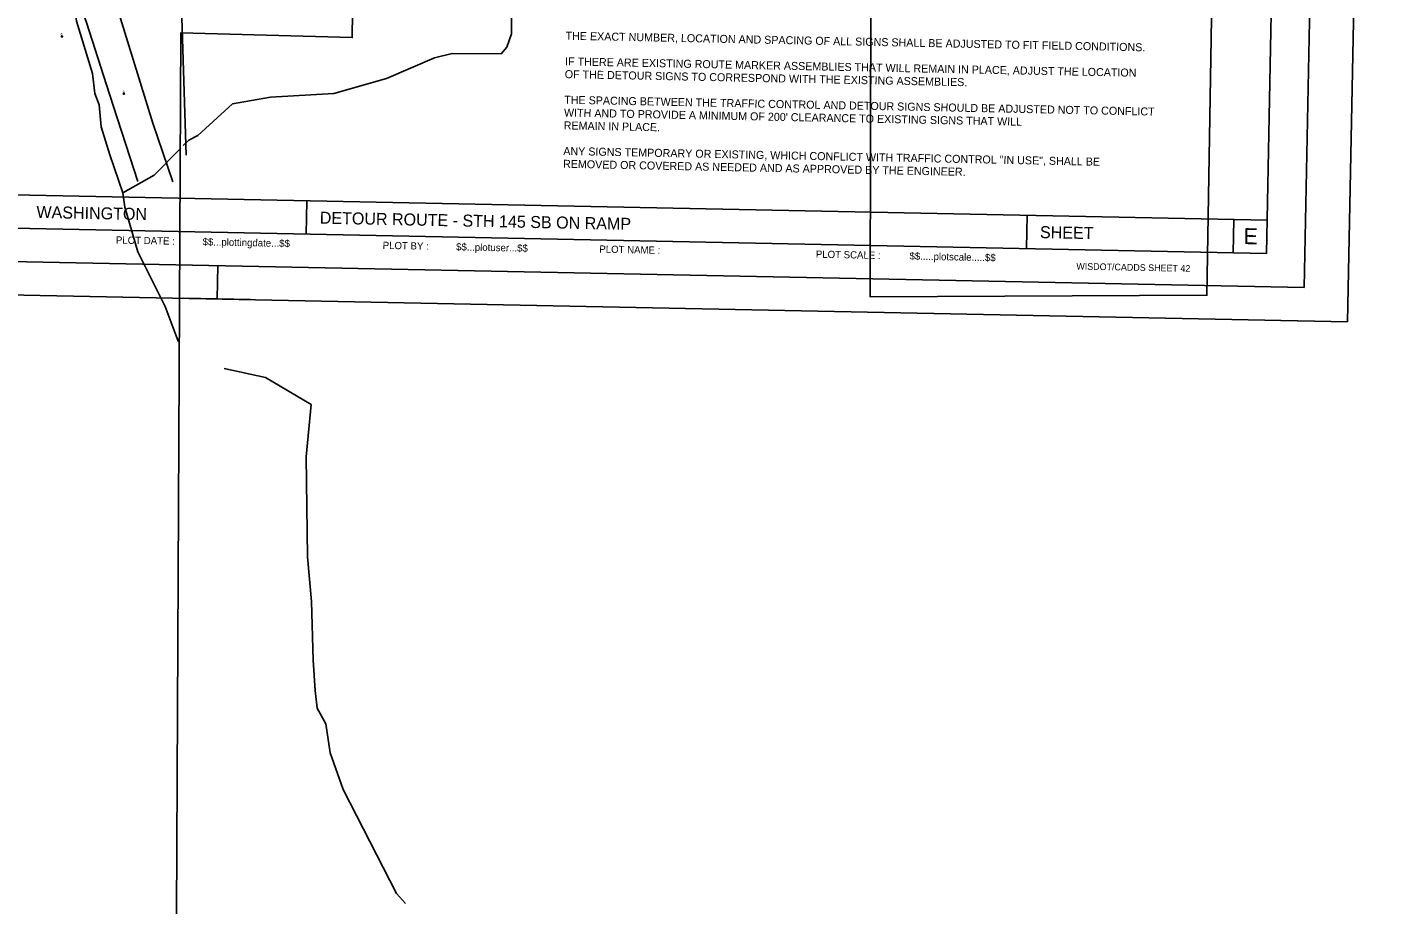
# Model space of a CAD drawing. Extents: x 331323 to 388339, y 121519 to 205315.
# Drawn here: x 361475 to 371668, y 121807 to 128453 of the extents above; entities that cross this region are included whole.
import ezdxf

# ---------------------------------------------------------------- set-up
doc = ezdxf.new("R2010")
doc.units = 0
for name, color, linetype in [('CA-TEXT', 7, 'Continuous'), ('E_SOIL_BORE1 [KAPUR_CADDS_LEVELS]', 7, 'Continuous'), ('E_SOIL_BORE2 [KAPUR_CADDS_LEVELS]', 7, 'Continuous'), ('Level 2', 7, 'Continuous'), ('Level 21', 7, 'Continuous'), ('Level 4', 7, 'Continuous'), ('Level 57', 7, 'Continuous'), ('P_MARK', 7, 'Continuous'), ('P_RDWY_Text', 7, 'Continuous'), ('PLT_Sheet_Border', 7, 'Continuous'), ('PLT_Sheet_Info', 7, 'Continuous')]:
    doc.layers.add(name, color=color, linetype=linetype)

msp = doc.modelspace()

# ---------------------------------------------------------------- linework, layer by layer
at = {"layer": 'Level 2'}
for points in [[(361798, 130230), (361948, 129376), (362176, 128518), (362416, 127734), (362567, 127294)], [(361525, 129517), (361674, 129157), (361920, 128489), (362093, 127950), (362304, 127295)]]:
    msp.add_lwpolyline(points, dxfattribs=at)
at = {"layer": 'Level 21'}
msp.add_lwpolyline([(375076, 132102), (370943, 132185), (370895, 130740), (370392, 130742), (370319, 126443), (367795, 126431), (367808, 132231), (366120, 132233), (366136, 131513), (366392, 131512), (366390, 130783), (366031, 131091), (365085, 131112), (365090, 131495), (364323, 131507), (364297, 130440), (364589, 130440), (364573, 129673), (363929, 129678), (363912, 128375), (362626, 128410), (362594, 121807)], dxfattribs=at)
at = {"layer": 'Level 4'}
msp.add_lwpolyline([(362628, 130213), (362617, 129083), (362666, 127494)], dxfattribs=at)
at = {"layer": 'Level 57'}
for points in [[(361568, 129209), (361699, 129008), (361748, 128907), (361764, 128807), (361813, 128698), (361845, 128498), (361966, 128105), (361982, 127955), (362014, 127871), (362029, 127705), (362094, 127496), (362192, 127212)], [(362645, 127565), (362687, 127607), (362754, 127640), (363015, 127879), (363299, 127927), (363775, 127956), (364168, 128069), (364528, 128224), (364661, 128256), (365028, 128253), (365071, 128302), (365105, 128402), (365108, 128727)], [(362192, 127212), (362426, 127343), (362627, 127546)], [(362192, 127212), (362207, 127103), (362304, 126769), (362509, 126359), (362607, 126099), (362619, 126087)], [(362951, 125895), (363263, 125827), (363603, 125624), (363566, 125232), (363576, 124482), (363606, 124149), (363619, 123707), (363633, 123482), (363649, 123348), (363714, 123231), (363746, 123014), (363843, 122738), (364245, 121959), (364311, 121884)]]:
    msp.add_lwpolyline(points, dxfattribs=at)
at = {"layer": 'P_MARK'}
for p, q in [((361731, 128383), (361741, 128383)), ((361736, 128388), (361736, 128378)), ((362195, 127954), (362205, 127954)), ((362200, 127959), (362200, 127949))]:
    msp.add_line(p, q, dxfattribs=at)
for centre in [(361736, 128383), (362200, 127954)]:
    msp.add_circle(centre, 5, dxfattribs=at)
for centre, radius, start, end in [((361736, 128383), 4.5, 89.9869, 179.9869), ((361736, 128383), 4, 89.9869, 179.9869), ((361736, 128383), 3.5, 89.9869, 179.9869), ((361736, 128383), 3, 89.9869, 179.9869), ((361736, 128383), 2.5, 89.9869, 179.9869), ((361736, 128383), 2, 89.9869, 179.9869), ((361736, 128383), 1.5, 89.9869, 179.9869), ((361736, 128383), 1, 89.9869, 179.9869), ((361736, 128383), 4.5, 269.9869, 359.9869), ((361736, 128383), 4, 269.9869, 359.9869), ((361736, 128383), 3.5, 269.9869, 359.9869), ((361736, 128383), 3, 269.9869, 359.9869), ((361736, 128383), 2.5, 269.9869, 359.9869), ((361736, 128383), 2, 269.9869, 359.9869), ((361736, 128383), 1.5, 269.9869, 359.9869), ((361736, 128383), 1, 269.9869, 359.9869), ((361736, 128383), 0.5, 269.9869, 359.9869), ((361736, 128383), 0.5, 89.9869, 179.9869), ((362200, 127954), 4.5, 89.9869, 179.9869), ((362200, 127954), 4, 89.9869, 179.9869), ((362200, 127954), 3.5, 89.9869, 179.9869), ((362200, 127954), 3, 89.9869, 179.9869), ((362200, 127954), 2.5, 89.9869, 179.9869), ((362200, 127954), 2, 89.9869, 179.9869), ((362200, 127954), 1.5, 89.9869, 179.9869), ((362200, 127954), 1, 89.9869, 179.9869), ((362200, 127954), 0.5, 89.9869, 179.9869), ((362200, 127954), 4.5, 269.9869, 359.9869), ((362200, 127954), 4, 269.9869, 359.9869), ((362200, 127954), 3.5, 269.9869, 359.9869), ((362200, 127954), 3, 269.9869, 359.9869), ((362200, 127954), 2.5, 269.9869, 359.9869), ((362200, 127954), 2, 269.9869, 359.9869), ((362200, 127954), 1.5, 269.9869, 359.9869), ((362200, 127954), 1, 269.9869, 359.9869), ((362200, 127954), 0.5, 269.9869, 359.9869)]:
    msp.add_arc(centre, radius, start, end, dxfattribs=at)
at = {"layer": 'P_RDWY_Text'}
msp.add_lwpolyline([(354598, 137585), (371594, 137243), (371373, 126245), (354376, 126587)], close=True, dxfattribs=at)
at = {"layer": 'PLT_Sheet_Border'}
for points in [[(354376, 126587), (371373, 126245), (371594, 137243), (354598, 137585)], [(354501, 126835), (371048, 126502), (371259, 136999), (354713, 137333)]]:
    msp.add_lwpolyline(points, close=True, dxfattribs=at)
at = {"layer": 'PLT_Sheet_Info'}
for p, q in [((370765, 126757), (370967, 136755)), ((355024, 127324), (370770, 127007)), ((363567, 126902), (363572, 127152)), ((355019, 127074), (370765, 126757)), ((368966, 126794), (368971, 127044)), ((370515, 126762), (370520, 127012)), ((371373, 126245), (371383, 126745)), ((362899, 126416), (362904, 126666)), ((362649, 126421), (363149, 126411)), ((370873, 126255), (371373, 126245))]:
    msp.add_line(p, q, dxfattribs=at)

# ---------------------------------------------------------------- texts
at = {"layer": 'CA-TEXT'}
for s, p in [('THE EXACT NUMBER, LOCATION AND SPACING OF ALL SIGNS SHALL BE ADJUSTED TO FIT FIELD CONDITIONS.', (365511, 128359)), ('IF THERE ARE EXISTING ROUTE MARKER ASSEMBLIES THAT WILL REMAIN IN PLACE, ADJUST THE LOCATION ', (365507, 128167)), ('OF THE DETOUR SIGNS TO CORRESPOND WITH THE EXISTING ASSEMBLIES. ', (365505, 128071)), ('THE SPACING BETWEEN THE TRAFFIC CONTROL AND DETOUR SIGNS SHOULD BE ADJUSTED NOT TO CONFLICT', (365501, 127879)), ("WITH AND TO PROVIDE A MINIMUM OF 200' CLEARANCE TO EXISTING SIGNS THAT WILL", (365499, 127783)), ('REMAIN IN PLACE.', (365497, 127687)), ('ANY SIGNS TEMPORARY OR EXISTING, WHICH CONFLICT WITH TRAFFIC CONTROL "IN USE", SHALL BE', (365494, 127495)), ('REMOVED OR COVERED AS NEEDED AND AS APPROVED BY THE ENGINEER.', (365492, 127399))]:
    msp.add_text(s, height=60, rotation=358.8462, dxfattribs=at).set_placement(p)
at = {"layer": 'E_SOIL_BORE1 [KAPUR_CADDS_LEVELS]'}
msp.add_text('B1', height=10, rotation=89.9869, dxfattribs=at).set_placement((361737, 128392))
at = {"layer": 'E_SOIL_BORE2 [KAPUR_CADDS_LEVELS]'}
for s, p in [('B1', (361740, 128390)), ('B2', (362203, 127961))]:
    msp.add_text(s, height=10, rotation=89.9869, dxfattribs=at).set_placement(p)
at = {"layer": 'PLT_Sheet_Info'}
for s, height, p in [('WASHINGTON          ', 90, (361544, 127023)), ('DETOUR ROUTE - STH 145 SB ON RAMP                    ', 90, (363668, 126980)), ('SHEET ', 90, (369067, 126872)), ('E', 120, (370593, 126827)), ('PLOT DATE :', 54, (362140, 126831)), ('$$...plottingdate...$$', 54, (362790, 126818)), ('PLOT BY :', 54, (364140, 126791)), ('$$...plotuser...$$', 54, (364690, 126780)), ('PLOT NAME :                      ', 54, (365764, 126763)), ('PLOT SCALE : ', 54, (367387, 126725)), ('$$.....plotscale.....$$', 54, (368089, 126711)), ('WISDOT/CADDS SHEET 42', 50, (369340, 126636))]:
    msp.add_text(s, height=height, rotation=358.8462, dxfattribs=at).set_placement(p)

doc.saveas('drawing.dxf')
